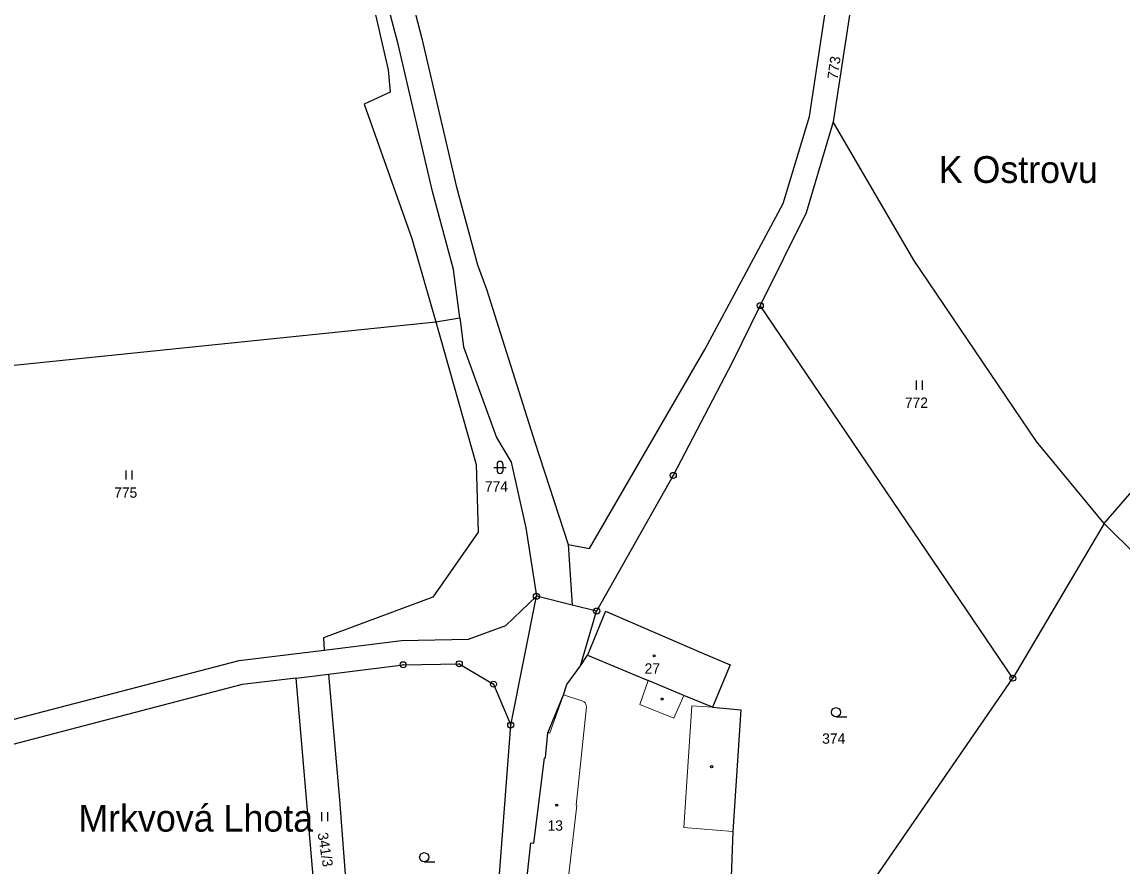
# Model space of a CAD drawing. Extents: x -719614 to -717765, y -1095834 to -1093862.
# Drawn here: x -719079.2 to -718898.5, y -1094321.1 to -1094182.4 of the extents above; entities that cross this region are included whole.
import ezdxf
from ezdxf.enums import TextEntityAlignment as Align

# ---------------------------------------------------------------- set-up
doc = ezdxf.new("R2010")
doc.units = 0
doc.header["$LTSCALE"] = 0.68
for name, color, linetype, lineweight in [('1', 7, 'Continuous', 25), ('3', 7, 'Continuous', 25), ('4', 7, 'Continuous', 13), ('5', 7, 'Continuous', 25), ('8', 7, 'Continuous', 25)]:
    doc.layers.add(name, color=color, linetype=linetype, lineweight=lineweight)
doc.layers.add('2', color=7, linetype='Continuous')
doc.layers.add('7', color=7, linetype='Continuous')

msp = doc.modelspace()

# ---------------------------------------------------------------- linework, layer by layer
at = {"layer": '1'}
for p, q in [((-718901.4, -1094264.73), (-718792.98, -1094138.94)), ((-719023.81, -1094169.28), (-719019.07, -1094190.2)), ((-719017.58, -1094169.63), (-719013.5, -1094185.04)), ((-719017.38, -1094186), (-719021.42, -1094170.76)), ((-718949.83, -1094197.86), (-718946.98, -1094179.04)), ((-718943.16, -1094180.53), (-718945.93, -1094198.76)), ((-719013.5, -1094185.04), (-719007.89, -1094209.24)), ((-719011.77, -1094210.21), (-719017.38, -1094186)), ((-719019.07, -1094190.2), (-719018.69, -1094193.89)), ((-719018.69, -1094193.89), (-719022.97, -1094195.85)), ((-719022.97, -1094195.85), (-719015.18, -1094217.93)), ((-718954.12, -1094212.18), (-718949.83, -1094197.86)), ((-718945.93, -1094198.76), (-718950.39, -1094213.67)), ((-718932.65, -1094221.47), (-718945.93, -1094198.76)), ((-719007.89, -1094209.24), (-719004.39, -1094222.24)), ((-719008.32, -1094223.02), (-719011.77, -1094210.21)), ((-718967.03, -1094236.14), (-718954.12, -1094212.18)), ((-718950.39, -1094213.67), (-718957.91, -1094228.92)), ((-719015.18, -1094217.93), (-719011.21, -1094231.58)), ((-718912.51, -1094251.22), (-718932.65, -1094221.47)), ((-719007.29, -1094230.92), (-719008.32, -1094223.02)), ((-719004.39, -1094222.24), (-719002.88, -1094226.23)), ((-719002.88, -1094226.23), (-718994.92, -1094251.37)), ((-718957.91, -1094228.92), (-718962.51, -1094238.27)), ((-718916.41, -1094290.11), (-718957.91, -1094228.92)), ((-719011.21, -1094231.58), (-719007.29, -1094230.92)), ((-719007.29, -1094230.92), (-719006.67, -1094235.71)), ((-719136.66, -1094244.44), (-719011.21, -1094231.58)), ((-719011.21, -1094231.58), (-719004.56, -1094255)), ((-719006.67, -1094235.71), (-719001.22, -1094250.6)), ((-718985.98, -1094268.84), (-718967.03, -1094236.14)), ((-718962.51, -1094238.27), (-718972.21, -1094256.81)), ((-719001.22, -1094250.6), (-718998.82, -1094254.66)), ((-718994.92, -1094251.37), (-718989.46, -1094268.16)), ((-718901.4, -1094264.73), (-718912.51, -1094251.22)), ((-719004.56, -1094255), (-719004.28, -1094266.14)), ((-718998.82, -1094254.66), (-718996.43, -1094265.44)), ((-718972.21, -1094256.81), (-718984.79, -1094279.09)), ((-718996.43, -1094265.44), (-718994.68, -1094276.66)), ((-718901.4, -1094264.73), (-718916.41, -1094290.11)), ((-718895.91, -1094270.11), (-718901.4, -1094264.73)), ((-719004.28, -1094266.14), (-719011.73, -1094276.82)), ((-718989.46, -1094268.16), (-718985.98, -1094268.84)), ((-718989.46, -1094268.16), (-718988.82, -1094278.1)), ((-719011.73, -1094276.82), (-719029.67, -1094283.51)), ((-718999.7, -1094281.47), (-718994.68, -1094276.66)), ((-718998.9, -1094297.81), (-718994.68, -1094276.66)), ((-718988.82, -1094278.1), (-718994.68, -1094276.66)), ((-718984.79, -1094279.09), (-718988.82, -1094278.1)), ((-718987.46, -1094288.08), (-718984.79, -1094279.09)), ((-718983.31, -1094279.11), (-718986.27, -1094286.34)), ((-719005.85, -1094283.72), (-718999.7, -1094281.47)), ((-719029.67, -1094283.51), (-719029.56, -1094285.49)), ((-719029.56, -1094285.49), (-719016.86, -1094283.91)), ((-719016.86, -1094283.91), (-719005.85, -1094283.72)), ((-719043.53, -1094287.2), (-719029.56, -1094285.49)), ((-718987.46, -1094288.08), (-718986.27, -1094286.34)), ((-718986.27, -1094286.34), (-718976.33, -1094290.5)), ((-719098.52, -1094301.52), (-719043.53, -1094287.2)), ((-719028.87, -1094289.43), (-719016.58, -1094287.91)), ((-719016.58, -1094287.91), (-719007.37, -1094287.75)), ((-719007.37, -1094287.75), (-719001.74, -1094291.09)), ((-718989.69, -1094291.17), (-718987.46, -1094288.08)), ((-718962.83, -1094287.91), (-718965.75, -1094294.89)), ((-719034.15, -1094290.08), (-719043.04, -1094291.17)), ((-719034.15, -1094290.08), (-719028.87, -1094289.43)), ((-719028.43, -1094357), (-719034.15, -1094290.08)), ((-719028.87, -1094289.43), (-719027.06, -1094310.11)), ((-718970.47, -1094292.93), (-718976.33, -1094290.5)), ((-718939.5, -1094323.68), (-718916.41, -1094290.11)), ((-719043.04, -1094291.17), (-719098.35, -1094305.6)), ((-719001.74, -1094291.09), (-718998.9, -1094297.81)), ((-718990.23, -1094292.85), (-718989.69, -1094291.17)), ((-718992.79, -1094299.11), (-718990.23, -1094292.85)), ((-718965.75, -1094294.89), (-718970.47, -1094292.93)), ((-718965.75, -1094294.89), (-718961.09, -1094295.3)), ((-718961.09, -1094295.3), (-718962.42, -1094315.26)), ((-719001.6, -1094333.67), (-718998.9, -1094297.81)), ((-718993.21, -1094303.16), (-718992.79, -1094299.11)), ((-718995.12, -1094317.22), (-718993.35, -1094303.23)), ((-718993.35, -1094303.23), (-718993.21, -1094303.16)), ((-719027.06, -1094310.11), (-719024.61, -1094341.99)), ((-718962.42, -1094315.26), (-718962.73, -1094324.2)), ((-718997.49, -1094333.99), (-718995.58, -1094317.16)), ((-718995.58, -1094317.16), (-718995.12, -1094317.22))]:
    msp.add_line(p, q, dxfattribs=at)
msp.add_lwpolyline([(-718983.31, -1094279.11), (-718967.5, -1094285.94), (-718962.83, -1094287.91)], dxfattribs=at)
at = {"layer": '3'}
for p, q in [((-718932.231, -1094242.74), (-718932.231, -1094241.24)), ((-718931.23, -1094242.74), (-718931.23, -1094241.24)), ((-719062.121, -1094257.5), (-719062.121, -1094256)), ((-719061.12, -1094257.5), (-719061.12, -1094256)), ((-719001.661, -1094255.501), (-718999.659, -1094255.501)), ((-719001.161, -1094255.001), (-719001.161, -1094256.002)), ((-719000.159, -1094256.002), (-719000.159, -1094255.001)), ((-718945.453, -1094296.45), (-718943.703, -1094296.45)), ((-719029.961, -1094313.61), (-719029.961, -1094312.11)), ((-719028.96, -1094313.61), (-719028.96, -1094312.11)), ((-719013.123, -1094320.26), (-719011.373, -1094320.26))]:
    msp.add_line(p, q, dxfattribs=at)
for centre in [(-718945.4529, -1094295.6998), (-719013.1229, -1094319.5098)]:
    msp.add_circle(centre, 0.75, dxfattribs=at)
for centre, start, end in [((-719000.66, -1094255.0009), 0, 180), ((-719000.66, -1094256.0009), 180, 359.98789)]:
    msp.add_arc(centre, 0.5, start, end, dxfattribs=at)
at = {"layer": '4'}
for p, q in [((-718976.33, -1094290.5), (-718977.7, -1094294.42)), ((-718992.46, -1094299.11), (-718990.23, -1094292.85)), ((-718990.23, -1094292.85), (-718987.05, -1094293.88)), ((-718972.1, -1094296.66), (-718970.47, -1094292.93)), ((-718986.48, -1094294.8), (-718988.18, -1094310.98)), ((-718977.7, -1094294.42), (-718972.1, -1094296.66)), ((-718969.14, -1094294.65), (-718970.47, -1094314.65)), ((-718965.75, -1094294.89), (-718969.14, -1094294.65)), ((-718992.79, -1094299.11), (-718992.46, -1094299.11)), ((-718988.07, -1094310.99), (-718990.45, -1094331.45)), ((-718988.18, -1094310.98), (-718988.07, -1094310.99)), ((-718970.47, -1094314.65), (-718962.42, -1094315.26))]:
    msp.add_line(p, q, dxfattribs=at)
msp.add_lwpolyline([(-718987.05, -1094293.88), (-718986.85, -1094293.995), (-718986.685, -1094294.155), (-718986.564, -1094294.351), (-718986.494, -1094294.57), (-718986.48, -1094294.8)], dxfattribs=at)
at = {"layer": '5'}
for centre in [(-718975.3268, -1094286.4292), (-718974.0268, -1094293.5392), (-718965.8968, -1094304.6292), (-718991.3468, -1094310.9492)]:
    msp.add_circle(centre, 0.175, dxfattribs=at)
at = {"layer": '8'}
for centre, radius in [((-718957.91, -1094228.9199), 0.5), ((-718957.91, -1094228.9199), 0.0303), ((-718972.21, -1094256.8099), 0.5), ((-718972.21, -1094256.8099), 0.0303), ((-718994.68, -1094276.6599), 0.5), ((-718994.68, -1094276.6599), 0.0303), ((-718984.79, -1094279.0899), 0.5), ((-718984.79, -1094279.0899), 0.0303), ((-719016.58, -1094287.9099), 0.5), ((-719016.58, -1094287.9099), 0.0303), ((-719007.37, -1094287.7499), 0.5), ((-719007.37, -1094287.7499), 0.0303), ((-719001.74, -1094291.0899), 0.5), ((-718916.41, -1094290.1099), 0.5), ((-718916.41, -1094290.1099), 0.0303), ((-719001.74, -1094291.0899), 0.0303), ((-718998.9, -1094297.8099), 0.5), ((-718998.9, -1094297.8099), 0.0303)]:
    msp.add_circle(centre, radius, dxfattribs=at)

# ---------------------------------------------------------------- texts
at = {"layer": '2'}
for s, rotation, p in [('773', 82, (-718944.9504, -1094189.9783)), ('341/3', 279, (-719030.2086, -1094318.394))]:
    msp.add_text(s, height=1.7, rotation=rotation, dxfattribs=at).set_placement(p, align=Align.CENTER)
for s, p in [('772', (-718932.249, -1094245.722)), ('774', (-719001.259, -1094259.482)), ('775', (-719062.169, -1094260.482)), ('27', (-718975.639, -1094289.365)), ('374', (-718945.839, -1094300.875)), ('13', (-718991.589, -1094315.155))]:
    msp.add_text(s, height=1.7, dxfattribs=at).set_placement(p, align=Align.CENTER)
at = {"layer": '7'}
for s, p in [('K Ostrovu', (-718928.59, -1094208.78)), ('Mrkvová Lhota', (-719069.96, -1094315.31))]:
    msp.add_text(s, height=4.4, dxfattribs=at).set_placement(p)

doc.saveas('drawing.dxf')
